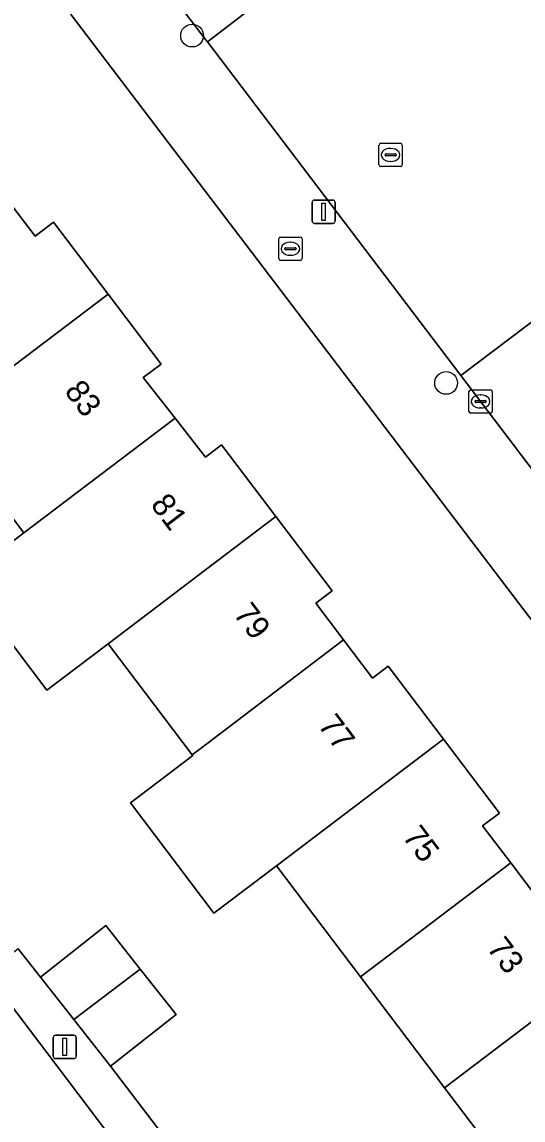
# Model space of a CAD drawing. Extents: x 160030 to 160839, y 385325 to 386450.
# Drawn here: x 160492.09 to 160513.68, y 385659.77 to 385707.05 of the extents above; entities that cross this region are included whole.
import ezdxf

# ---------------------------------------------------------------- set-up
doc = ezdxf.new("R2010")
doc.units = 0
for name, color, linetype in [('IMGEO_Boom', 7, 'Continuous'), ('IMGEO_Brandkraan', 7, 'Continuous'), ('IMGEO_Erf', 7, 'Continuous'), ('IMGEO_Kolk', 7, 'Continuous'), ('IMGEO_Lichtmast', 7, 'Continuous'), ('IMGEO_Pand', 7, 'Continuous'), ('IMGEO_Pand_nummerreeks', 7, 'Continuous'), ('IMGEO_Rijbaan_lokaal_open', 7, 'Continuous'), ('IMGEO_Rioolput', 7, 'Continuous'), ('IMGEO_Voetpad_open', 7, 'Continuous')]:
    doc.layers.add(name, color=color, linetype=linetype)

msp = doc.modelspace()

# ---------------------------------------------------------------- linework, layer by layer
at = {"layer": 'IMGEO_Boom'}
for centre in [(160499.42, 385706.464), (160510.365, 385691.507)]:
    msp.add_circle(centre, 0.489, dxfattribs=at)
at = {"layer": 'IMGEO_Brandkraan'}
for p, q in [((160503.156, 385696.861), (160503.156, 385697.713)), ((160503.231, 385697.787), (160504.083, 385697.787)), ((160504.157, 385697.713), (160504.157, 385696.861)), ((160503.415, 385697.281), (160503.415, 385697.293)), ((160503.853, 385697.244), (160503.455, 385697.244)), ((160503.458, 385697.33), (160503.856, 385697.33)), ((160503.644, 385697.567), (160503.669, 385697.567)), ((160503.899, 385697.293), (160503.899, 385697.281)), ((160504.083, 385696.787), (160503.231, 385696.787)), ((160503.667, 385697.007), (160503.642, 385697.007))]:
    msp.add_line(p, q, dxfattribs=at)
for points in [[(160503.156, 385696.861), (160503.156, 385697.713)], [(160503.231, 385697.787), (160504.083, 385697.787)], [(160504.157, 385697.713), (160504.157, 385696.861)], [(160504.083, 385696.787), (160503.231, 385696.787)]]:
    msp.add_lwpolyline(points, dxfattribs=at)
for centre, radius, start, end in [((160503.233, 385697.711), 0.0765, 91.552, 178.448), ((160503.233, 385697.711), 0.0765, 91.552, 178.448), ((160504.081, 385697.711), 0.0765, 1.552, 88.448), ((160504.081, 385697.711), 0.0765, 1.552, 88.448), ((160503.455, 385697.29), 0.0403, 85.8775, 175.7526), ((160503.452, 385697.28), 0.0366, 178.938, 274.7102), ((160503.856, 385697.287), 0.043, 264.8664, 352.4533), ((160503.86, 385697.292), 0.0386, 1.7309, 96.639), ((160503.233, 385696.863), 0.0765, 181.552, 268.448), ((160503.233, 385696.863), 0.0765, 181.552, 268.448), ((160504.081, 385696.863), 0.0765, 271.552, 358.448), ((160504.081, 385696.863), 0.0765, 271.552, 358.448)]:
    msp.add_arc(centre, radius, start, end, dxfattribs=at)
for centre, major_axis, ratio, start_param, end_param in [((160503.643, 385697.287), (-0.387, 0.002), 0.722429, 4.712389, 7.853982), ((160503.668, 385697.287), (-0.39, 0.002), 0.717154, 1.570796, 4.712389)]:
    msp.add_ellipse(centre, major_axis=major_axis, ratio=ratio, start_param=start_param, end_param=end_param, dxfattribs=at)
at = {"layer": 'IMGEO_Erf'}
for points in [[(160533.41, 385655.858), (160500, 385699.746), (160471.388, 385737.358)], [(160491.382, 385699.514), (160492.656, 385697.833), (160493.453, 385698.437), (160495.803, 385695.337), (160498.09, 385692.32), (160497.32, 385691.737), (160498.687, 385689.994), (160500, 385688.318), (160500.684, 385688.837), (160503.023, 385685.752), (160505.451, 385682.549), (160504.754, 385682.022), (160505.951, 385680.443), (160507.2, 385678.795), (160507.873, 385679.305), (160510.249, 385676.171), (160512.663, 385672.986), (160511.938, 385672.437), (160513.149, 385670.84), (160514.384, 385669.21)], [(160513.927, 385656.371), (160510.302, 385661.153), (160506.678, 385665.934), (160503.053, 385670.715), (160500.361, 385668.674), (160496.762, 385673.422), (160499.454, 385675.463), (160499.428, 385675.497), (160495.804, 385680.279), (160493.165, 385678.279), (160489.54, 385683.06), (160492.179, 385685.06), (160488.554, 385689.841)], [(160491.934, 385667.136), (160492.888, 385665.924), (160495.712, 385668.146), (160497.189, 385666.269), (160498.729, 385664.312), (160495.905, 385662.09), (160500.192, 385656.48), (160503.031, 385658.631), (160504.47, 385656.732), (160506.019, 385654.686), (160503.18, 385652.535), (160507.452, 385646.916), (160510.227, 385649.04), (160511.754, 385647.046), (160508.979, 385644.922), (160514.628, 385637.478), (160533.261, 385651.698)]]:
    msp.add_lwpolyline(points, dxfattribs=at)
at = {"layer": 'IMGEO_Kolk'}
for p, q in [((160511.35, 385690.284), (160511.35, 385691.136)), ((160511.425, 385691.21), (160512.277, 385691.21)), ((160512.351, 385691.136), (160512.351, 385690.284)), ((160511.609, 385690.704), (160511.609, 385690.716)), ((160512.047, 385690.667), (160511.649, 385690.667)), ((160511.652, 385690.753), (160512.05, 385690.753)), ((160511.838, 385690.99), (160511.863, 385690.99)), ((160512.093, 385690.716), (160512.093, 385690.704)), ((160512.277, 385690.21), (160511.425, 385690.21)), ((160511.861, 385690.43), (160511.836, 385690.43))]:
    msp.add_line(p, q, dxfattribs=at)
for points in [[(160511.35, 385690.284), (160511.35, 385691.136)], [(160511.425, 385691.21), (160512.277, 385691.21)], [(160512.351, 385691.136), (160512.351, 385690.284)], [(160512.277, 385690.21), (160511.425, 385690.21)]]:
    msp.add_lwpolyline(points, dxfattribs=at)
for centre, radius, start, end in [((160511.427, 385691.134), 0.0765, 91.552, 178.448), ((160511.427, 385691.134), 0.0765, 91.552, 178.448), ((160512.275, 385691.134), 0.0765, 1.552, 88.448), ((160512.275, 385691.134), 0.0765, 1.552, 88.448), ((160511.649, 385690.713), 0.0403, 85.8775, 175.7526), ((160511.646, 385690.703), 0.0366, 178.938, 274.7102), ((160512.05, 385690.71), 0.043, 264.8664, 352.4533), ((160512.054, 385690.715), 0.0386, 1.7309, 96.639), ((160511.427, 385690.286), 0.0765, 181.552, 268.448), ((160511.427, 385690.286), 0.0765, 181.552, 268.448), ((160512.275, 385690.286), 0.0765, 271.552, 358.448), ((160512.275, 385690.286), 0.0765, 271.552, 358.448)]:
    msp.add_arc(centre, radius, start, end, dxfattribs=at)
for centre, major_axis, ratio, start_param, end_param in [((160511.837, 385690.71), (-0.387, 0.002), 0.722429, 4.712389, 7.853982), ((160511.862, 385690.71), (-0.39, 0.002), 0.717154, 1.570796, 4.712389)]:
    msp.add_ellipse(centre, major_axis=major_axis, ratio=ratio, start_param=start_param, end_param=end_param, dxfattribs=at)
at = {"layer": 'IMGEO_Lichtmast'}
for p, q in [((160504.59, 385698.481), (160504.59, 385699.281)), ((160504.59, 385699.281), (160504.59, 385698.481)), ((160504.69, 385699.381), (160505.48, 385699.381)), ((160505.48, 385699.381), (160504.69, 385699.381)), ((160505.58, 385699.281), (160505.58, 385698.481)), ((160505.58, 385698.481), (160505.58, 385699.281)), ((160505.48, 385698.381), (160504.69, 385698.381)), ((160504.69, 385698.381), (160505.48, 385698.381)), ((160493.44, 385662.516), (160493.44, 385663.316)), ((160493.44, 385663.316), (160493.44, 385662.516)), ((160493.54, 385663.416), (160494.33, 385663.416)), ((160494.33, 385663.416), (160493.54, 385663.416)), ((160494.43, 385663.316), (160494.43, 385662.516)), ((160494.43, 385662.516), (160494.43, 385663.316)), ((160494.33, 385662.416), (160493.54, 385662.416)), ((160493.54, 385662.416), (160494.33, 385662.416))]:
    msp.add_line(p, q, dxfattribs=at)
for points in [[(160505.01, 385699.256), (160505.16, 385699.256), (160505.16, 385698.506), (160505.01, 385698.506), (160505.01, 385699.256)], [(160493.86, 385663.291), (160494.01, 385663.291), (160494.01, 385662.541), (160493.86, 385662.541), (160493.86, 385663.291)]]:
    msp.add_lwpolyline(points, dxfattribs=at)
for centre, start, end in [((160504.69, 385699.281), 90, 180), ((160504.69, 385699.281), 90, 180), ((160505.48, 385699.281), 0, 90), ((160505.48, 385699.281), 360, 90), ((160504.69, 385698.481), 180, 270), ((160504.69, 385698.481), 180, 270), ((160505.48, 385698.481), 270, 0), ((160505.48, 385698.481), 270, 0), ((160493.54, 385663.316), 90, 180), ((160493.54, 385663.316), 90, 180), ((160494.33, 385663.316), 0, 90), ((160494.33, 385663.316), 360, 90), ((160493.54, 385662.516), 180, 270), ((160493.54, 385662.516), 180, 270), ((160494.33, 385662.516), 270, 0), ((160494.33, 385662.516), 270, 0)]:
    msp.add_arc(centre, 0.1, start, end, dxfattribs=at)
at = {"layer": 'IMGEO_Pand'}
for points in [[(160488.554, 385689.841), (160495.803, 385695.337), (160493.453, 385698.437), (160492.656, 385697.833), (160491.382, 385699.514), (160484.93, 385694.623)], [(160492.179, 385685.06), (160498.687, 385689.994), (160497.32, 385691.737), (160498.09, 385692.32), (160495.803, 385695.337), (160488.554, 385689.841)], [(160503.023, 385685.752), (160500.684, 385688.837), (160500, 385688.318), (160498.687, 385689.994), (160492.179, 385685.06), (160489.54, 385683.06), (160493.165, 385678.279), (160495.804, 385680.279), (160500, 385683.46)], [(160499.428, 385675.497), (160500, 385675.931), (160505.951, 385680.443), (160504.754, 385682.022), (160505.451, 385682.549), (160503.023, 385685.752), (160500, 385683.46), (160495.804, 385680.279)], [(160507.873, 385679.305), (160507.2, 385678.795), (160505.951, 385680.443), (160500, 385675.931), (160499.428, 385675.497), (160499.454, 385675.463), (160496.762, 385673.422), (160500.361, 385668.674), (160503.053, 385670.715), (160510.249, 385676.171)], [(160506.678, 385665.934), (160513.149, 385670.84), (160511.938, 385672.437), (160512.663, 385672.986), (160510.249, 385676.171), (160503.053, 385670.715)], [(160510.302, 385661.153), (160517.549, 385666.647), (160515.16, 385669.798), (160514.384, 385669.21), (160513.149, 385670.84), (160506.678, 385665.934)], [(160497.189, 385666.269), (160495.712, 385668.146), (160492.888, 385665.924), (160494.325, 385664.098)], [(160513.927, 385656.371), (160520.413, 385661.289), (160519.155, 385662.949), (160519.915, 385663.525), (160517.549, 385666.647), (160510.302, 385661.153)], [(160494.325, 385664.098), (160495.905, 385662.09), (160498.729, 385664.312), (160497.189, 385666.269)]]:
    msp.add_lwpolyline(points, close=True, dxfattribs=at)
at = {"layer": 'IMGEO_Rijbaan_lokaal_open'}
for points in [[(160475.667, 385750), (160461.3, 385768.906), (160459.341, 385771.483), (160458.532, 385772.547), (160456.328, 385775.448), (160445.768, 385789.344), (160440.269, 385785.051), (160460.541, 385758.433), (160466.313, 385750.996), (160466.344, 385750.961), (160476.157, 385738.065), (160476.427, 385737.611), (160498.422, 385708.377), (160500, 385706.302), (160500.083, 385706.193), (160505.746, 385710.546), (160503.974, 385712.848), (160500, 385718.016), (160497.228, 385721.62), (160490.796, 385730.087)], [(160490.563, 385666.095), (160488.378, 385664.436), (160485.975, 385662.61), (160483.571, 385660.785), (160481.168, 385658.96), (160478.764, 385657.134), (160476.361, 385655.309), (160473.957, 385653.484), (160471.554, 385651.658), (160469.15, 385649.833), (160476.149, 385640.577), (160494.262, 385654.222), (160495.248, 385652.987), (160497.326, 385650.085), (160501.637, 385644.578), (160506.601, 385638.064), (160509.815, 385633.793), (160513.227, 385636.408), (160497.09, 385657.497)]]:
    msp.add_lwpolyline(points, close=True, dxfattribs=at)
for points in [[(160506.497, 385709.786), (160505.803, 385710.473), (160505.746, 385710.546), (160500.083, 385706.193), (160511.005, 385691.824), (160516.683, 385696.125), (160516.347, 385696.567)], [(160551.877, 385649.668), (160542.312, 385662.277), (160542.249, 385662.375), (160539.718, 385665.716), (160539.192, 385666.41), (160518.609, 385693.58), (160516.683, 385696.125), (160511.005, 385691.824), (160519.703, 385680.381), (160536.815, 385657.852), (160536.957, 385657.707), (160547.022, 385644.629), (160547.128, 385644.454), (160556.726, 385631.808)]]:
    msp.add_lwpolyline(points, dxfattribs=at)
at = {"layer": 'IMGEO_Rioolput'}
for p, q in [((160507.474, 385700.901), (160507.474, 385701.753)), ((160507.549, 385701.827), (160508.401, 385701.827)), ((160507.962, 385701.607), (160507.987, 385701.607)), ((160508.475, 385701.753), (160508.475, 385700.901)), ((160507.733, 385701.321), (160507.733, 385701.333)), ((160508.171, 385701.284), (160507.773, 385701.284)), ((160507.776, 385701.37), (160508.174, 385701.37)), ((160507.985, 385701.047), (160507.96, 385701.047)), ((160508.217, 385701.333), (160508.217, 385701.321)), ((160508.401, 385700.827), (160507.549, 385700.827))]:
    msp.add_line(p, q, dxfattribs=at)
for points in [[(160507.474, 385700.901), (160507.474, 385701.753)], [(160507.549, 385701.827), (160508.401, 385701.827)], [(160508.475, 385701.753), (160508.475, 385700.901)], [(160508.401, 385700.827), (160507.549, 385700.827)]]:
    msp.add_lwpolyline(points, dxfattribs=at)
for centre, radius, start, end in [((160507.551, 385701.751), 0.0765, 91.552, 178.448), ((160507.551, 385701.751), 0.0765, 91.552, 178.448), ((160508.399, 385701.751), 0.0765, 1.552, 88.448), ((160508.399, 385701.751), 0.0765, 1.552, 88.448), ((160507.773, 385701.33), 0.0403, 85.8775, 175.7526), ((160507.77, 385701.32), 0.0366, 178.938, 274.7102), ((160508.174, 385701.327), 0.043, 264.8664, 352.4533), ((160508.178, 385701.332), 0.0386, 1.7309, 96.639), ((160507.551, 385700.903), 0.0765, 181.552, 268.448), ((160507.551, 385700.903), 0.0765, 181.552, 268.448), ((160508.399, 385700.903), 0.0765, 271.552, 358.448), ((160508.399, 385700.903), 0.0765, 271.552, 358.448)]:
    msp.add_arc(centre, radius, start, end, dxfattribs=at)
for centre, major_axis, ratio, start_param, end_param in [((160507.961, 385701.327), (-0.387, 0.002), 0.722429, 4.712389, 7.853982), ((160507.986, 385701.327), (-0.39, 0.002), 0.717154, 1.570796, 4.712389)]:
    msp.add_ellipse(centre, major_axis=major_axis, ratio=ratio, start_param=start_param, end_param=end_param, dxfattribs=at)
at = {"layer": 'IMGEO_Voetpad_open'}
for points in [[(160469.447, 385739.909), (160471.388, 385737.358), (160500, 385699.746), (160533.41, 385655.858), (160533.531, 385655.877), (160536.981, 385651.632)], [(160536.815, 385657.852), (160519.703, 385680.381), (160511.005, 385691.824), (160500.083, 385706.193), (160500, 385706.302), (160498.422, 385708.377), (160476.427, 385737.611)]]:
    msp.add_lwpolyline(points, dxfattribs=at)
msp.add_lwpolyline([(160503.18, 385652.535), (160501.631, 385654.58), (160500.192, 385656.48), (160495.905, 385662.09), (160494.325, 385664.098), (160492.888, 385665.924), (160491.934, 385667.136), (160490.782, 385666.261), (160490.563, 385666.095), (160497.09, 385657.497), (160513.227, 385636.408), (160513.35, 385636.503), (160514.628, 385637.478), (160508.979, 385644.922), (160507.452, 385646.916)], close=True, dxfattribs=at)

# ---------------------------------------------------------------- texts
at = {"layer": 'IMGEO_Pand_nummerreeks'}
for s, rotation, p in [('83', 307.1959, (160493.89, 385691.145)), ('81', 307.1962, (160497.6, 385686.259)), ('79', 307.1959, (160501.171, 385681.553)), ('77', 307.1962, (160504.811, 385676.756)), ('75', 307.1959, (160508.451, 385671.96)), ('73', 307.1959, (160512.091, 385667.164))]:
    msp.add_text(s, height=1, rotation=rotation, dxfattribs=at).set_placement(p)

doc.saveas('drawing.dxf')
